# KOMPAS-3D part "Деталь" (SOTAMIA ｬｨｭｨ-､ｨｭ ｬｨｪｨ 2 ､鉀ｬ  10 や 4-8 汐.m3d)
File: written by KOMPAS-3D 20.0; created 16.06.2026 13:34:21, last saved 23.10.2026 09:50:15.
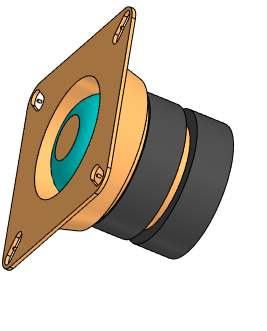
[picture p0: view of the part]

Document properties: Полное имя файла: D:\RicWork\Project-EPS32\box_compas\динамик\SOTAMIA мини-динамики 2 дюйма 10 Вт 4-8 Ом.m3d

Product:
- Part/product: Деталь
    Масса: 0.217029
  - Body: Тело 1
      Масса: 0.217207

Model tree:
1. Эскиз:1
2. Элемент выдавливания:1
     Расстояние 1 = 1
3. Эскиз:2  (with: Элемент выдавливания:1)
4. Элемент выдавливания:2
     Расстояние 1 = 10; Угол 1 = 15
5. Эскиз:7  (with: Элемент выдавливания:1, Элемент выдавливания:2)
6. Элемент выдавливания:15
     Расстояние 2 = 10
7. Эскиз:3  (with: Элемент выдавливания:2)
8. Элемент выдавливания:5
     Расстояние 1 = 2
9. Эскиз:4  (with: Элемент выдавливания:5)
10. Элемент выдавливания:6
     Расстояние 1 = 10
11. Эскиз:5  (with: Элемент выдавливания:6)
12. Элемент выдавливания:7
     Расстояние 1 = 3
13. Эскиз:8  (with: Элемент выдавливания:1, Элемент выдавливания:2)
14. Элемент выдавливания:12
     Расстояние 2 = 10
15. Эскиз:12  (with: Элемент выдавливания:7)
16. Эскиз:14  (with: Элемент выдавливания:12)
17. Элемент выдавливания:16
     Расстояние 1 = 10
18. Скругление:4  (with: Элемент выдавливания:16)
     Радиус = 8
19. Эскиз:15  (with: Элемент выдавливания:7)
20. Элемент выдавливания:17
     Расстояние 1 = 10
21. Массив по концентрической сетке:2  (with: Элемент выдавливания:15, Эскиз:7, Элемент выдавливания:2)  (4 pattern instances)
     Шаг 2 = 360
22. Скругление:5  (with: Элемент выдавливания:1)
     Радиус = 5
